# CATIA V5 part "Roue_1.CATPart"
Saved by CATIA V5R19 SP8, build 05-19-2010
Part number: Roue 1
Nomenclature: 70_R1
Bounding box of the stored display mesh (mm): x -3.874 to 3.874, y -3.884 to 3.884, z 0 to 16
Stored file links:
  C:\Users\rphgr\Desktop\0_Tapis_TC520B_vitesse\Roue_1.CATPart
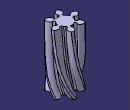
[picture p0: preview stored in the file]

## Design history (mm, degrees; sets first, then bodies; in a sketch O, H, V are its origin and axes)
External parameters (linked from other documents)
  External.Module = 0.9 mm
  External.Z = 6
  External.DiamPrimitif = 5.9582 mm {= External.ModuleApparent*External.Z}
  External.AnglePression = 20 deg
  External.x = 0
  External.DeportDenture = 0 mm {= External.x *External.ModuleApparent}
  External.DiamBase = 5.5989 mm {= External.DiamPrimitif *cos(External.AnglePression )}
  External.DiamPied = 3.7082 mm {= External.DiamPrimitif -2.5*External.Module +2*External.DeportDenture}
  External.DiamTete = 7.7582 mm {= External.DiamPrimitif +2*External.Module +2*External.DeportDenture}
  External.PhiPrimitif = 0.854 deg {= atan((sin(External.ThetaPrimitif*1rad)-External.ThetaPrimitif*cos(External.ThetaPrimitif*1rad))/(cos(External.ThetaPrimitif*1rad)+External.ThetaPrimitif*sin(External.ThetaPrimitif*1rad)))}
  External.PhiTete = 11.1513 deg {= atan((sin(External.ThetaTete*1rad)-External.ThetaTete*cos(External.ThetaTete*1rad))/(cos(External.ThetaTete*1rad)+External.ThetaTete*sin(External.ThetaTete*1rad)))}
  External.PhiSymetrie = 15 deg {= 180*1 deg/(2*External.Z )}
  External.CongePied = 0.342 mm {= 0.38*External.Module}
  External.AlphaCopie = 60 deg {= 360*1 deg/External.Z}
  External.AlphaSymetrieCopie = 30 deg {= External.AlphaCopie /2}
  External.LargeurDenture = 16 mm {= External.LargeurDent}
  External.ThetaPrimitif = 0.36397 {= sqrt(abs((External.DiamPrimitif*External.DiamPrimitif)/(External.DiamBase *External.DiamBase )-1))}
  External.ThetaTete = 0.959207 {= sqrt(abs((External.DiamTete*External.DiamTete)/(External.DiamBase *External.DiamBase )-1) )}
  External.Di = 5.7786 mm {= (External.DiamBase +External.DiamPrimitif )/2}
  External.Thetai = 0.255358 {= sqrt(abs((External.Di*External.Di)/(External.DiamBase*External.DiamBase)-1))}
  External.Phii = 0.3061 deg {= atan((sin(External.Thetai*1rad)-External.Thetai*cos(External.Thetai*1rad))/(cos(External.Thetai*1rad)+External.Thetai*sin(External.Thetai*1rad)))}
  External.Dj = 6.8582 mm {= (External.DiamTete+External.DiamPrimitif)/2}
  External.Thetaj = 0.707416 {= sqrt(abs((External.Dj*External.Dj)/(External.DiamBase*External.DiamBase)-1))}
  External.Phij = 5.2557 deg {= atan((sin(External.Thetaj*1rad)-External.Thetaj*cos(External.Thetaj*1rad))/(cos(External.Thetaj*1rad)+External.Thetaj*sin(External.Thetaj*1rad)))}
  External.Dk = 5.6887 mm {= (External.Di+External.DiamBase)/2}
  External.Thetak = 0.179851 {= sqrt(abs((External.Dk*External.Dk)/(External.DiamBase*External.DiamBase)-1))}
  External.Phik = 0.109 deg {= atan((sin(External.Thetak*1rad)-External.Thetak*cos(External.Thetak*1rad))/(cos(External.Thetak*1rad)+External.Thetak*sin(External.Thetak*1rad)))}
  External.Dl = 5.8684 mm {= (External.DiamPrimitif+External.Di)/2}
  External.Thetal = 0.31398 {= sqrt(abs((External.Dl*External.Dl)/(External.DiamBase*External.DiamBase)-1))}
  External.Phil = 0.5585 deg {= atan((sin(External.Thetal*1rad)-External.Thetal*cos(External.Thetal*1rad))/(cos(External.Thetal*1rad)+External.Thetal*sin(External.Thetal*1rad)))}
  External.Dm = 6.4082 mm {= (External.Dj+External.DiamPrimitif)/2}
  External.Thetam = 0.556773 {= sqrt(abs((External.Dm*External.Dm)/(External.DiamBase*External.DiamBase)-1))}
  External.Phim = 2.7929 deg {= atan((sin(External.Thetam*1rad)-External.Thetam*cos(External.Thetam*1rad))/(cos(External.Thetam*1rad)+External.Thetam*sin(External.Thetam*1rad)))}
  External.Dn = 7.3082 mm {= (External.DiamTete+External.Dj)/2}
  External.Thetan = 0.838926 {= sqrt(abs((External.Dn*External.Dn)/(External.DiamBase*External.DiamBase)-1))}
  External.Phin = 8.0728 deg {= atan((sin(External.Thetan*1rad)-External.Thetan*cos(External.Thetan*1rad))/(cos(External.Thetan*1rad)+External.Thetan*sin(External.Thetan*1rad)))}
  External.AngleHelice = 25 deg
  External.ModuleApparent = 0.993 mm {= External.Module /cos(External.AngleHelice )}
  External.SensDenture = -1
  External.LargeurDent = 16 mm
Body1 (main body)
  Sketch1 "EsquisseDent" on xy-plane, origin (0, 0, 0), H (1, 0, 0), V (0, 1, 0)
    construction circle A1 centre (0, 0) radius 2.9791
    construction circle A2 centre (0, 0) radius 2.7995
    construction circle A3 centre (0, 0) radius 1.8541
    construction circle A4 centre (0, 0) radius 3.8791
    point P1 (2.7995, 0)
    construction line L1 (2.7995, 0) -> (0, 0)
    point P2 (2.9788, 0.0444)
    construction line L2 (2.9788, 0.0444) -> (0, 0)
    point P3 (3.8059, 0.7502)
    construction line L3 (3.8059, 0.7502) -> (0, 0)
    construction line L4 (2.7995, 0) -> (2.7995, 3.9367)
    point P4 (2.7995, 0)
    point P6 (2.6201, 0.0444)
    construction line L5 (3.8059, 0.7502) -> (2.9788, 0.0444)
    point P7 (3.3923, 0.3973)
    point P8 (2.2066, 0.3973)
    spline S1 through (2.2066, 0.3973) (2.6201, 0.0444) (2.7995, 0) (2.8444, 0.0054) (2.8892, 0.0154) (2.9341, 0.0286) (2.9788, 0.0444) (3.2003, 0.1561) (3.4147, 0.3141) (3.6179, 0.5132) (3.8059, 0.7502)
    construction line L6 (0, 0) -> (5.0738, 1.4409)
    spline S2 through (2.086, 0.8217) (2.2524, 1.3393) (2.3816, 1.4714) (2.4227, 1.4904) (2.4661, 1.5054) (2.5112, 1.5178) (2.5575, 1.5278) (2.8047, 1.5492) (3.0701, 1.5275) (3.3476, 1.465) (3.6321, 1.3621)
    arc A5 centre (2.1952, -0.0647) radius 0.342 from (2.4219, 0.1913) to (1.8533, -0.0547) ccw
    point P11 (1.8533, -0.0547)
    arc A6 centre (0, 0) radius 3.8791 from (3.8059, 0.7502) to (3.6321, 1.3621) ccw
    point P13 (3.6321, 1.3621)
    arc A7 centre (1.8335, 1.2088) radius 0.342 from (1.548, 1.0206) to (2.1609, 1.1101) ccw
    point P15 (1.548, 1.0206)
    construction line L7 (0, 0) -> (2.9832, 3.0735)
    construction line L8 (0, 0) -> (4.9704, -1.2527)
    point P19 (1.2914, 1.3305)
    arc A8 centre (0, 0) radius 1.8541 from (1.548, 1.0206) to (1.2914, 1.3305) ccw
    point P20 (1.7979, -0.4531)
    arc A9 centre (0, 0) radius 1.8541 from (1.7979, -0.4531) to (1.8533, -0.0547) ccw
    line L9 (1.2914, 1.3305) -> (0, 0)
    line L10 (1.7979, -0.4531) -> (0, 0)
    construction circle A10 centre (0, 0) radius 2.8893
    construction line L11 (0, 0) -> (2.5698, 0.0137)
    point P22 (2.8892, 0.0154)
    construction circle A11 centre (0, 0) radius 3.4291
    construction line L12 (0, 0) -> (4.0022, 0.3682)
    point P24 (3.4147, 0.3141)
    point P25 (3.4147, 0.3141)
    point P26 (3.0701, 1.5275)
    point P27 (2.4661, 1.5054)
    construction circle A12 centre (0, 0) radius 2.8444
    construction line L13 (0, 0) -> (48.2618, 0.0918)
    point P29 (2.4227, 1.4904)
    construction line L14 (0, 0) -> (61.5448, 17.478)
    point P31 (2.8444, 0.0054)
    construction circle A13 centre (0, 0) radius 2.9342
    construction line L15 (0, 0) -> (57.3607, 0.5591)
    point P33 (2.9341, 0.0286)
    point P34 (2.5112, 1.5178)
    construction circle A14 centre (0, 0) radius 3.2041
    construction line L16 (0, 0) -> (65.6327, 3.2018)
    point P36 (3.2003, 0.1561)
    point P37 (2.8047, 1.5492)
    construction circle A15 centre (0, 0) radius 3.6541
    axis line L17 (0, 0) -> (58.7628, 8.3347)
    point P39 (3.3476, 1.465)
    point P40 (3.6179, 0.5132)
    point P42 (2.2066, 0.3973)
    point P43 (2.6201, 0.0444)
    point P44 (2.7995, 0)
    point P45 (2.9788, 0.0444)
    point P46 (3.8059, 0.7502)
    point P47 (3.6321, 1.3621)
    point P48 (2.086, 0.8217)
    point P49 (2.5575, 1.5278)
    point P50 (2.3816, 1.4714)
    point P51 (2.2524, 1.3393)
    point P52 (2.8892, 0.0154)
    point P53 (3.4147, 0.3141)
    point P54 (2.4661, 1.5054)
    point P55 (3.0701, 1.5275)
    point P56 (2.8444, 0.0054)
    point P57 (2.4227, 1.4904)
    point P58 (2.9341, 0.0286)
    point P59 (2.5112, 1.5178)
    point P60 (3.2003, 0.1561)
    point P61 (2.8047, 1.5492)
    point P62 (3.6179, 0.5132)
    point P63 (3.3476, 1.465)
    radius A1 = 2.9791 {= External.DiamPrimitif /2}
    radius A2 = 2.7995 {= External.DiamBase /2}
    radius A3 = 1.8541 {= External.DiamPied /2}
    radius A4 = 3.8791 {= External.DiamTete /2}
    angle L2 L1 = 0.854 {= External.PhiPrimitif}
    angle L3 L1 = 11.1513 {= External.PhiTete}
    angle L4 L1 = 90
    radius A5 = 0.342 {= External.CongePied}
    radius A7 = 0.342 {= External.CongePied}
    angle L7 L6 = 30 {= External.AlphaSymetrieCopie}
    angle L2 L6 = 15 {= External.PhiSymetrie}
    radius A10 = 2.8893 {= External.Di /2}
    angle L11 L1 = 0.3061 {= External.Phii}
    radius A11 = 3.4291 {= External.Dj /2}
    angle L12 L1 = 5.2557 {= External.Phij}
    radius A12 = 2.8444 {= External.Dk/2}
    angle L13 L1 = 0.109 {= External.Phik}
    angle L14 L2 = 15 {= External.PhiSymetrie}
    radius A13 = 2.9342 {= External.Dl /2}
    angle L15 L1 = 0.5585 {= External.Phil}
    radius A14 = 3.2041 {= External.Dm /2}
    angle L16 L1 = 2.7929 {= External.Phim}
    radius A15 = 3.6541 {= External.Dn/2}
    angle L17 L1 = 8.0728 {= External.Phin}
    coincidence: P1 A2, P1 H, P2 A1, P3 A4, P4 A2, P7 L5, P42 P8, P43 P6, P44 P1, P45 L5, P45 L2, P46 L5, P46 L3, P11 A3, P47 P13, P15 A3, P19 L7, P19 A3, P20 L8, P20 A3, P3 P46, P22 L11, P22 A10, P52 P22, P24 L12, P24 A11, P53 P24, P25 P53, P54 P27, P55 P26, P31 L13, P31 A12, P56 P31, P57 P29, P33 L15, P33 A13, P58 P33, P59 P34, P36 L16, P36 A14, P60 P36, P61 P37, P40 L17, P40 A15, P62 P40, P63 P39, O L9, O L10
    horizontal: L1 H
    tangency: L4 A2, A5 A3, A5 S1, A7 A3, A7 S2, A8 A5, A9 A5
    symmetry: P6 P2 L4, P8 P7 L4, P46 P47 L6, P42 P48 L6, P45 P49 L6, P44 P50 L6, P43 P51 L6, L8 L7 L6, P26 P25 L6, P27 P22 L6, P29 P31 L14, P34 P33 L14, P37 P36 L14, P39 P40 L14
    midpoint: P7 L5
    parallelism: L9 L7, L10 L8
    concentricity: A10 A2, A11 A1
  Translate1: ToTransfor Sketch1, Direction (0, 0, 1), Length 16 {= External.LargeurDenture}
  Rotate1: ToTransfor Translate1, Axis Z axis, Angle -68.2333 {= External.SensDenture *atan(2*External.LargeurDenture/External.DiamPrimitif*tan(External.AngleHelice))}
  Translate2: ToTransfor Sketch1, Direction (0, 0, 1), Length 8 {= External.LargeurDenture/2}
  Rotate2: ToTransfor Translate2, Axis Z axis, Angle -51.3894 {= External.SensDenture *atan(External.LargeurDenture/(External.DiamPrimitif)*tan(External.AngleHelice))}
  Translate3: ToTransfor Sketch1, Direction (0, 0, 1), Length 12 {= 3/4*External.LargeurDenture}
  Rotate3: ToTransfor Translate3, Axis Z axis, Angle -61.9694 {= External.SensDenture*atan(3*External.LargeurDenture/(2*External.DiamPrimitif)*tan(External.AngleHelice))}
  Translate4: ToTransfor Sketch1, Direction (0, 0, 1), Length 4 {= External.LargeurDenture/4}
  Rotate4: ToTransfor Translate4, Axis Z axis, Angle -32.0507 {= External.SensDenture*atan(External.LargeurDenture/(2*External.DiamPrimitif)*tan(External.AngleHelice))}
  Loft1: solid, Sections (Sketch1; Rotate4; Rotate2; Rotate3; Rotate1)
  CircPattern1: of the body so far, instances 6 {= External.Z}, angular step 60 {= External.AlphaCopie}, axis from Z axis
  AxisSystem1: origin (0, 0, 0), X (1, 0, 0), Y (0, 1, 0), Z (0, 0, 1)
  Plane1: type Offset, RefPlane xy-plane, Offset 16 {= External.LargeurDenture}, reversed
